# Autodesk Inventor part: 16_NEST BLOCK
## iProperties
Created: 2006-12
Part Number: 16_NEST BLOCK
Document SubType Name: Modeling
Designer: RDGodetteII
Material: Steel, High Strength Low Alloy
Mass: 2472.33 g
Surface Area: 388.175 cm^2
Volume: 315.349 cm^3
Density: 7.84 g/cm^3
Author: RDGodetteII
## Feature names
1. Extrusion1
2. Hole2
3. Rectangular Pattern2
4. Extrusion3
